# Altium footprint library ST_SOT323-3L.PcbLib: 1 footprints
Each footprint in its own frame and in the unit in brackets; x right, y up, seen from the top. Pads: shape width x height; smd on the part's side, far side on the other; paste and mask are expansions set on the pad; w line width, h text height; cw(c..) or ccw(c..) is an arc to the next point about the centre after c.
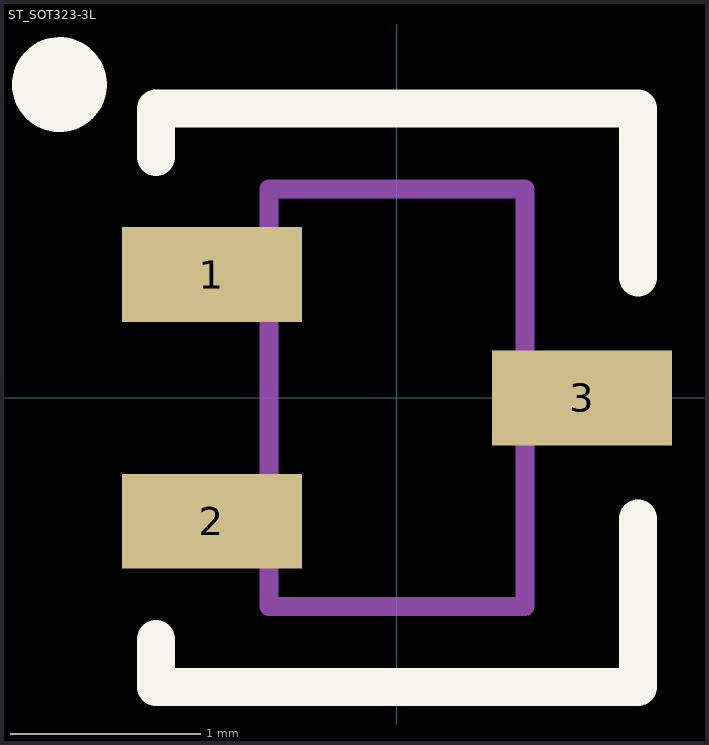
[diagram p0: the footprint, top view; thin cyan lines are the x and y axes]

## ST_SOT323-3L [mm]
height 1.1
pads (3):
  rect 0.95x0.5 smd: 1(-0.975,0.65) 2(-0.975,-0.65) 3(0.975,0)
Top Overlay:
  circle w0.25: c-1.778,1.651 r0.125
  lines w0.2: -1.27,-1.27 -1.27,-1.524 1.27,-1.524 1.27,-0.635 ; -1.27,1.27 -1.27,1.524 1.27,1.524 1.27,0.635
Mechanical 13:
  lines w0.1: -0.675,-1.1 0.675,-1.1 0.675,1.1 -0.675,1.1 -0.675,-1.1
3D body "ST_SOT323-3L.step": height 1.1, standoff 0, extent -1.3,-1.1 1.3,1.1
